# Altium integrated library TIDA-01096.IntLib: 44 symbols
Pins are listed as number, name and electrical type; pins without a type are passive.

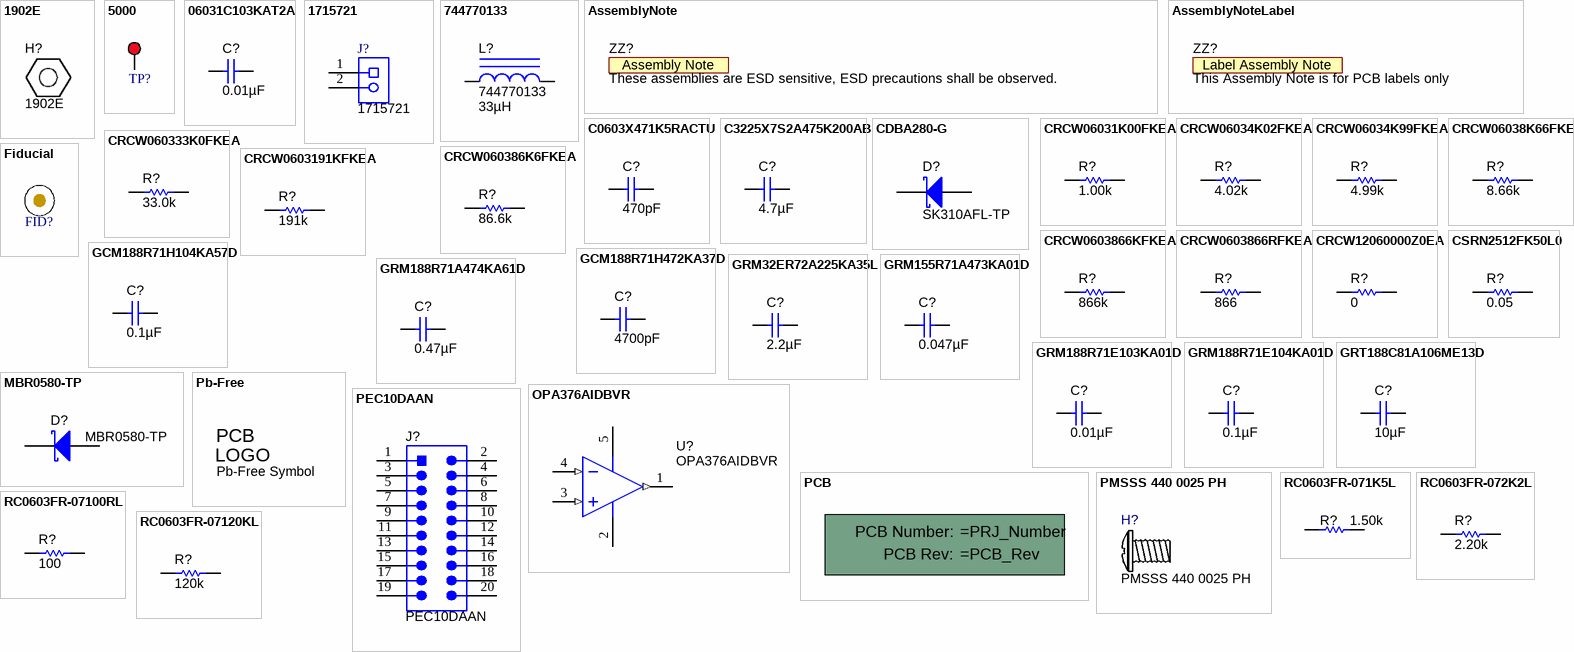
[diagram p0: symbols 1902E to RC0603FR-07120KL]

## 1902E
designator H?
Standoff, Hex, 1"L #4-40 Nylon; Manufacturer: Keystone; CompType: Hardware; SymbolCreator: a0412235
footprint Keystone_1902E

## 5000
designator TP?  (value not drawn)
Test Point, Miniature, Red, TH; Manufacturer: Keystone; CompType: Test Point Loop; U/M: EA
footprint Keystone5000
pins: 1

## 06031C103KAT2A
designator C?, comment ValueDisplayed: 0.01µF  (hidden comment: GCM188R72A103KA37D)
10000pF ±10% 100V X7R Ceramic Capacitor -55°C ~ 125°C Surface Mount, MLCC 0603 (1608 Metric) 0.063" L x 0.031" W (1.60mm x 0.80mm); Manufacturer: Murata Electronics North America; Polarized: N; Value: 0.01uF; U/M: EA; Cap_F: 0.00000001; Tolerance_%: 10; ESR_ohm: 0.098; Value1: 0.098 ohm; VDC_V: 100; TaMin_C: -55; TaMax_C: 125; Cap_Case: 0603; SizeArea_mm2: 1.28; SizeAreaWB_mm2: 4.68; SizeX_mm: 1.6; SizeY_mm: 0.8; SizeZ_mm: 1; AEC Category: Q200
signal-integrity model Cap
simulation model Cap
footprint 0603
footprint 0603M
footprint 0603L
footprint 0603_HV
footprint 0603S
pins: 1, 2

## 1715721
designator J?
Terminal Block, 5.08 mm, 2x1, TH; Manufacturer: Phoenix Contact; SymbolCreator: a0412235; Pitch_mm: 5.08; Gender: Female; Row_Count: 1; ContactFinish: Tin; Current_A: 17.5; Voltage_V: 400; Cert_CSA: Y; Cert_CULUS: N
footprint PhoenixContact_1715721
pins: 1, 2

## 744770133
designator L?  ValueDisplayed: 33µH
Inductor, Shielded Drum Core, Ferrite, 33uH, 3.2A, 0.047 ohm, SMD; Manufacturer: Wurth Elektronik eiSos; Ind_H: 33.0E-6; Imax_A: 3.2; Irms: 3.2A @ 40C rise; Isat: 3.6A @ 10% inductance drop; DCR_ohm: 0.047; U/M: EA
signal-integrity model Inductor
simulation model Inductor
footprint WE-PD-XL
pins: 1, 2

## AssemblyNote
designator ZZ?, comment These assemblies are ESD sensitive, ESD precautions shall be observed.  (no BOM)
SymbolCreator: codlsc; CompType: AssemblyNote
footprint AssemblyNote

## AssemblyNoteLabel
designator ZZ?, comment This Assembly Note is for PCB labels only  (no BOM)
SymbolCreator: a0412235
footprint AssemblyNoteLabel

## C0603X471K5RACTU
designator C?  ValueDisplayed: 470pF  (hidden comment: C0603X471K5RACTU)
CAP, CERM, 470 pF, 50 V, +/- 10%, X7R, 0603; Manufacturer: Kemet; Polarized: N; CompType: Capacitor; Value: 470pF; U/M: EA; Cap_F: 0.00000000047; Tolerance_%: 10; Value1: Unknown; VDC_V: 50; Value2: 50V; TaMin_C: -55; TaMax_C: 125; Cap_Case: 0603; AEC Category: Q200; SizeArea_mm2: 1.28; SizeAreaWB_mm2: 4.68; SizeX_mm: 1.6; SizeY_mm: 0.8; SizeZ_mm: 1
signal-integrity model Cap
simulation model Cap
footprint 0603
footprint 0603M
footprint 0603L
footprint 0603_HV
footprint 0603S
pins: 1, 2

## C3225X7S2A475K200AB
designator C?, comment ValueDisplayed: 4.7µF  (hidden comment: GRJ32DC72A475KE11L)
4.7µF ±10% 100V X7S Ceramic Capacitor -55°C ~ 125°C Surface Mount, MLCC 1210 (3225 Metric) 0.126" L x 0.098" W (3.20mm x 2.50mm); Manufacturer: Murata Electronics North America; Polarized: N; Value: 4.7uF; U/M: EA; Cap_F: 0.0000047; Tolerance_%: 10; ESR_ohm: 0.004236; Value1: 0.004236 ohm; VDC_V: 100; IRMS_A: 3.57337; TaMin_C: -55; TaMax_C: 125; Cap_Case: 1210_220; SizeArea_mm2: 8; SizeAreaWB_mm2: 14.7; SizeX_mm: 3.2; SizeY_mm: 2.5; SizeZ_mm: 2.2; AEC Category: Q200
signal-integrity model Cap
simulation model Cap
footprint 1210_220
footprint 1210_220M
footprint 1210_220L
pins: 1, 2

## CDBA280-G
designator D?, comment SK310AFL-TP
DIODE SCHOTTKY 100V 3A DO221AC; Manufacturer: Micro Commercial Co; U/M: EA; Vf_V: 0.85; Value: 80V; Value1: 2A; Value2: 0.85V; Io_A: 2; Vr_V: 80; TJmax_C: 125; SizeAreaWB_mm2: 37.3428; SizeArea_mm2: 16.3228; SizeX_mm: 5.59; SizeY_mm: 2.92; SizeZ_mm: 2.87; AEC Category: Q101
signal-integrity model Diode
footprint SMA
pins: 1 K, 2 A

## CRCW06031K00FKEA
designator R?  ValueDisplayed: 1.00k  (hidden comment: CRCW06031K00FKEA)
RES, 1.00 k, 1%, 0.1 W, 0603; Manufacturer: Vishay-Dale; CompType: Resistor; Value: 1.00k; Res_ohm: 1000; Value_Code: 1k00; Tolerance_%: 1; Power_W: 0.1; Value2: 0.1W; VDC_V: 75; TempCo: 100 ppm/C; SizeArea_mm2: 1.28; SizeX_mm: 1.6; SizeY_mm: 0.8; EIA_Code: E96; U/M: EA; AEC Category: Q200
signal-integrity model Resistor
simulation model Resistor
footprint 0603
footprint 0603M
footprint 0603L
footprint 0603_HV
footprint 0603S
pins: 1, 2

## CRCW06034K02FKEA
designator R?  ValueDisplayed: 4.02k  (hidden comment: CRCW06034K02FKEA)
RES, 4.02 k, 1%, 0.1 W, 0603; Manufacturer: Vishay-Dale; CompType: Resistor; Value: 4.02k; Res_ohm: 4020; Value_Code: 4k02; Tolerance_%: 1; Power_W: 0.1; Value2: 0.1W; VDC_V: 75; TempCo: 100 ppm/C; SizeArea_mm2: 1.28; SizeX_mm: 1.6; SizeY_mm: 0.8; EIA_Code: E96; U/M: EA; AEC Category: Q200
signal-integrity model Resistor
simulation model Resistor
footprint 0603
footprint 0603M
footprint 0603L
footprint 0603_HV
footprint 0603S
pins: 1, 2

## CRCW06034K99FKEA
designator R?  ValueDisplayed: 4.99k  (hidden comment: CRCW06034K99FKEA)
RES, 4.99 k, 1%, 0.1 W, 0603; Manufacturer: Vishay-Dale; CompType: Resistor; Value: 4.99k; Res_ohm: 4990; Value_Code: 4k99; Tolerance_%: 1; Power_W: 0.1; Value2: 0.1W; VDC_V: 75; TempCo: 100 ppm/C; SizeArea_mm2: 1.28; SizeX_mm: 1.6; SizeY_mm: 0.8; EIA_Code: E96; U/M: EA; AEC Category: Q200
signal-integrity model Resistor
simulation model Resistor
footprint 0603
footprint 0603M
footprint 0603L
footprint 0603_HV
footprint 0603S
pins: 1, 2

## CRCW06038K66FKEA
designator R?  ValueDisplayed: 8.66k  (hidden comment: CRCW06038K66FKEA)
RES, 8.66 k, 1%, 0.1 W, 0603; Manufacturer: Vishay-Dale; CompType: Resistor; Value: 8.66k; Res_ohm: 8660; Value_Code: 8k66; Tolerance_%: 1; Power_W: 0.1; Value2: 0.1W; VDC_V: 75; TempCo: 100 ppm/C; EIA_Code: E96; U/M: EA; AEC Category: Q200; SizeArea_mm2: 1.28; SizeX_mm: 1.6; SizeY_mm: 0.8
signal-integrity model Resistor
simulation model Resistor
footprint 0603
footprint 0603M
footprint 0603L
footprint 0603_HV
footprint 0603S
pins: 1, 2

## CRCW060333K0FKEA
designator R?  ValueDisplayed: 33.0k  (hidden comment: CRCW060333K0FKEA)
RES, 33.0 k, 1%, 0.1 W, 0603; Manufacturer: Vishay-Dale; CompType: Resistor; Value: 33.0k; Res_ohm: 33000; Value_Code: 33k0; Tolerance_%: 1; Power_W: 0.1; Value2: 0.1W; VDC_V: 75; TempCo: 100 ppm/C; U/M: EA; AEC Category: Q200; SizeArea_mm2: 1.28; SizeX_mm: 1.6; SizeY_mm: 0.8
signal-integrity model Resistor
simulation model Resistor
footprint 0603
footprint 0603M
footprint 0603L
footprint 0603_HV
footprint 0603S
pins: 1, 2

## CRCW060386K6FKEA
designator R?  ValueDisplayed: 86.6k  (hidden comment: CRCW060386K6FKEA)
RES, 86.6 k, 1%, 0.1 W, 0603; Manufacturer: Vishay-Dale; CompType: Resistor; Value: 86.6k; Res_ohm: 86600; Value_Code: 86k6; Tolerance_%: 1; Power_W: 0.1; Value2: 0.1W; VDC_V: 75; TempCo: 100 ppm/C; EIA_Code: E96; U/M: EA; AEC Category: Q200
signal-integrity model Resistor
simulation model Resistor
footprint 0603
footprint 0603M
footprint 0603L
footprint 0603_HV
footprint 0603S
pins: 1, 2

## CRCW0603191KFKEA
designator R?  ValueDisplayed: 191k  (hidden comment: CRCW0603191KFKEA)
RES, 191 k, 1%, 0.1 W, 0603; Manufacturer: Vishay-Dale; CompType: Resistor; Value: 191k; Res_ohm: 191000; Tolerance_%: 1; Power_W: 0.1; Value2: 0.1W; VDC_V: 75; TempCo: 100 ppm/C; SizeArea_mm2: 1.28; SizeX_mm: 1.6; SizeY_mm: 0.8; EIA_Code: E96; U/M: EA; AEC Category: Q200
signal-integrity model Resistor
simulation model Resistor
footprint 0603
footprint 0603M
footprint 0603L
footprint 0603_HV
footprint 0603S
pins: 1, 2

## CRCW0603866KFKEA
designator R?  ValueDisplayed: 866k  (hidden comment: CRCW0603866KFKEA)
RES, 866 k, 1%, 0.1 W, 0603; Manufacturer: Vishay-Dale; CompType: Resistor; Value: 866k; Res_ohm: 866000; Tolerance_%: 1; Power_W: 0.1; Value2: 0.1W; VDC_V: 75; TempCo: 100 ppm/C; EIA_Code: E96; U/M: EA; AEC Category: Q200; SizeArea_mm2: 1.28; SizeX_mm: 1.6; SizeY_mm: 0.8
signal-integrity model Resistor
simulation model Resistor
footprint 0603
footprint 0603M
footprint 0603L
footprint 0603_HV
footprint 0603S
pins: 1, 2

## CRCW0603866RFKEA
designator R?  ValueDisplayed: 866  (hidden comment: CRCW0603866RFKEA)
RES, 866, 1%, 0.1 W, 0603; Manufacturer: Vishay-Dale; CompType: Resistor; Value: 866; Value_Code: 866R; Tolerance_%: 1; Power_W: 0.1; Value2: 0.1W; VDC_V: 75; TempCo: 100 ppm/C; EIA_Code: E96; U/M: EA; AEC Category: Q200; SizeArea_mm2: 1.28; SizeX_mm: 1.6; SizeY_mm: 0.8
signal-integrity model Resistor
simulation model Resistor
footprint 0603
footprint 0603M
footprint 0603L
footprint 0603_HV
footprint 0603S
pins: 1, 2

## CRCW12060000Z0EA
designator R?  ValueDisplayed: 0  (hidden comment: CRCW12060000Z0EA)
RES, 0, 5%, 0.25 W, 1206; Manufacturer: Vishay-Dale; CompType: Resistor; Value: 0; Value_Code: 0000; Tolerance_%: 5; Power_W: 0.25; Value2: 0.25W; VDC_V: 200; TempCo: 200 ppm/C; EIA_Code: E24; U/M: EA; AEC Category: Q200; SizeArea_mm2: 5.12; SizeX_mm: 3.2; SizeY_mm: 1.6; SizeZ_mm: 1.35
signal-integrity model Resistor
simulation model Resistor
footprint 1206
footprint 1206M
footprint 1206L
pins: 1, 2

## CSRN2512FK50L0
designator R?, comment ValueDisplayed: 0.05  (hidden comment: CSRN2512FK50L0CT-ND)
RES, 0.05, 1%, 2 W, 2512; Manufacturer: Stackpole Electronics Inc; CompType: Resistor; Value: 0.05; Value_Code: R050; Tolerance_%: 1; Power_W: 2; Value2: 2W; TempCo: 200 ppm/C; EIA_Code: E96; U/M: EA; AEC Category: Q200
signal-integrity model Resistor
simulation model Resistor
footprint 2512
footprint 2512M
footprint 2512L
pins: 1, 2

## Fiducial
designator FID?  (value not drawn)
Fiducial mark.  There is nothing to buy or mount.; SymbolCreator: codlsc
footprint Fiducial10-30
footprint Fiducial10-20
footprint Fiducial15-30
footprint Fiducial20-40
footprint Fiducial6.4-20

## GCM188R71H104KA57D
designator C?  ValueDisplayed: 0.1µF  (hidden comment: GCM188R71H104KA57D)
CAP, CERM, 0.1 µF, 50 V, +/- 10%, X7R, 0603; Manufacturer: MuRata; Polarized: N; CompType: Capacitor; Value: 0.1uF; U/M: EA; Cap_F: 0.0000001; Tolerance_%: 10; ESR_ohm: 0.02; Value1: 0.02 ohm; VDC_V: 50; Value2: 50V; IRMS_A: 1.84; TaMin_C: -55; TaMax_C: 125; Cap_Case: 0603; SizeArea_mm2: 1.28; SizeAreaWB_mm2: 4.68; SizeX_mm: 1.6; SizeY_mm: 0.8; SizeZ_mm: 1; AEC Category: Q200
signal-integrity model Cap
simulation model Cap
footprint 0603
footprint 0603M
footprint 0603L
footprint 0603_HV
footprint 0603S
pins: 1, 2

## GCM188R71H472KA37D
designator C?, comment ValueDisplayed: 4700pF  (hidden comment: GCM188R72A103KA37D)
10000pF ±10% 100V X7R Ceramic Capacitor -55°C ~ 125°C Surface Mount, MLCC 0603 (1608 Metric) 0.063" L x 0.031" W (1.60mm x 0.80mm); Manufacturer: Maruta; Polarized: N; Value: 4700pF; U/M: EA; Cap_F: 0.0000000047; Tolerance_%: 10; Value1: Unknown; VDC_V: 50; Value2: 50V; TaMin_C: -55; TaMax_C: 125; Cap_Case: 0603; AEC Category: Q200; AEC Qualified: Y; AEC Grade: 1
signal-integrity model Cap
simulation model Cap
footprint 0603
footprint 0603M
footprint 0603L
footprint 0603_HV
footprint 0603S
pins: 1, 2

## GRM32ER72A225KA35L
designator C?  ValueDisplayed: 2.2µF  (hidden comment: GRM32ER72A225KA35L)
CAP, CERM, 2.2 µF, 100 V, +/- 10%, X7R, 1210; Manufacturer: MuRata; Polarized: N; CompType: Capacitor; Value: 2.2uF; U/M: EA; Cap_F: 0.0000022; Tolerance_%: 10; ESR_ohm: 0.007; Value1: 0.007 ohm; VDC_V: 100; Value2: 100V; IRMS_A: 4.4; TaMin_C: -55; TaMax_C: 125; Cap_Case: 1210; AEC Category: Q200
signal-integrity model Cap
simulation model Cap
footprint 1210_270
footprint 1210_270M
footprint 1210_270L
pins: 1, 2

## GRM155R71A473KA01D
designator C?  ValueDisplayed: 0.047µF  (hidden comment: GRM155R71A473KA01D)
CAP, CERM, 0.047 µF, 10 V, +/- 10%, X7R, 0402; Manufacturer: MuRata; Polarized: N; CompType: Capacitor; Value: 0.047uF; U/M: EA; Cap_F: 0.000000047; Tolerance_%: 10; Value1: Unknown; Value2: 10V; TaMin_C: -55; TaMax_C: 125; Cap_Case: 0402; AEC Category: Q200; SizeArea_mm2: 0.5; SizeAreaWB_mm2: 3; SizeX_mm: 1; SizeZ_mm: 0.6
signal-integrity model Cap
simulation model Cap
footprint 0402
footprint 0402M
footprint 0402L
footprint 0402S
pins: 1, 2

## GRM188R71A474KA61D
designator C?  ValueDisplayed: 0.47µF  (hidden comment: GRM188R71A474KA61D)
CAP, CERM, 0.47 µF, 10 V, +/- 10%, X7R, 0603; Manufacturer: MuRata; Polarized: N; CompType: Capacitor; Value: 0.47uF; U/M: EA; Cap_F: 0.00000047; Tolerance_%: 10; Value1: Unknown; Value2: 10V; TaMin_C: -55; TaMax_C: 125; Cap_Case: 0603; AEC Category: Q200; SizeArea_mm2: 1.28; SizeAreaWB_mm2: 4.68; SizeX_mm: 1.6; SizeY_mm: 0.8; SizeZ_mm: 1
signal-integrity model Cap
simulation model Cap
footprint 0603
footprint 0603M
footprint 0603L
footprint 0603_HV
footprint 0603S
pins: 1, 2

## GRM188R71E103KA01D
designator C?  ValueDisplayed: 0.01µF  (hidden comment: GRM188R71E103KA01D)
CAP, CERM, 0.01 µF, 25 V, +/- 10%, X7R, 0603; Manufacturer: MuRata; Polarized: N; CompType: Capacitor; Value: 0.01uF; U/M: EA; Cap_F: 0.00000001; Tolerance_%: 10; Value1: Unknown; VDC_V: 25; Value2: 25V; TaMin_C: -55; TaMax_C: 125; Cap_Case: 0603; SizeArea_mm2: 1.28; SizeAreaWB_mm2: 4.68; SizeX_mm: 1.6; SizeY_mm: 0.8; SizeZ_mm: 1; AEC Category: Q200
signal-integrity model Cap
simulation model Cap
footprint 0603
footprint 0603M
footprint 0603L
footprint 0603_HV
footprint 0603S
pins: 1, 2

## GRM188R71E104KA01D
designator C?  ValueDisplayed: 0.1µF  (hidden comment: GRM188R71E104KA01D)
CAP, CERM, 0.1 µF, 25 V, +/- 10%, X7R, 0603; Manufacturer: MuRata; Polarized: N; CompType: Capacitor; Value: 0.1uF; U/M: EA; Cap_F: 0.0000001; Tolerance_%: 10; Value1: Unknown; VDC_V: 25; Value2: 25V; TaMin_C: -55; TaMax_C: 125; Cap_Case: 0603; SizeArea_mm2: 1.28; SizeAreaWB_mm2: 4.68; SizeX_mm: 1.6; SizeY_mm: 0.8; SizeZ_mm: 1; AEC Category: Q200
signal-integrity model Cap
simulation model Cap
footprint 0603
footprint 0603M
footprint 0603L
footprint 0603_HV
footprint 0603S
pins: 1, 2

## GRT188C81A106ME13D
designator C?  ValueDisplayed: 10µF  (hidden comment: GRT188C81A106ME13D)
CAP, CERM, 10 µF, 10 V, +/- 20%, X6S, AEC-Q200 Grade 2, 0603; Manufacturer: MuRata; Polarized: N; CompType: Capacitor; Value: 10uF; U/M: EA; Cap_F: 0.00001; Tolerance_%: 20; Value1: Unknown; VDC_V: 10; Value2: 10V; TaMin_C: -55; TaMax_C: 105; Cap_Case: 0603; AEC Category: Q200; AEC Qualified: Y; AEC Grade: 2
signal-integrity model Cap
simulation model Cap
footprint 0603
footprint 0603M
footprint 0603L
footprint 0603_HV
footprint 0603S
pins: 1, 2

## MBR0580-TP
designator D?
Diode, Schottky, 80 V, 0.5 A, SOD-123; Manufacturer: Micro Commercial Components; U/M: EA; Vf_V: 0.8; Value: 80V; Value1: 0.5A; Value2: 0.8V; Io_A: 0.5; Vr_V: 80; TJmax_C: 150; SizeAreaWB_mm2: 13.095; SizeArea_mm2: 6.545; SizeX_mm: 3.85; SizeY_mm: 1.7; SizeZ_mm: 1.35; AEC Category: Q101
signal-integrity model Diode
footprint SOD-123
pins: 1 K, 2 A

## OPA376AIDBVR
designator U?
Precision, Low Noise, Low Iq Operational Amplifier, 2.2 to 5.5 V, -40 to 125 degC, 5-pin SOT23 (DBV0005A), Green (RoHS & no Sb/Br); Manufacturer: Texas Instruments; Alternate PartNumber: Equivalent; CMRR(Min)(dB): 76; IIB(Max)(pA): 10; Iq per channel(Max)(mA): 0.95; Number of Channels: 1; Offset Drift(Typ)(uV/C): 0.32; Slew Rate(Typ)(V/us): 2; Sub Family: Low Input Bias Current Amp (<=10pA), Low Noise Amp (<=10nV/rtHz), Low Offset Voltage Amplifier (<=500uV), Low Supply Voltage Amplifier (<=2.7V), Precision Amplifier; Total Supply Voltage(Max)(+5V is 5, +/-5V is 10): 5.5; Total Supply Voltage(Min)(+5V is 5, +/-5V is 10): 2.2; Vio (25C)(Max)(mV): 0.025; Vn at 1kHz(Typ)(nV/rtHz): 7.5
footprint DBV0005A_N (SOT23, 5-Leads, Body 2.9x1.6mm, Pitch 0.95mm, IPC Medium Density)
footprint DBV0005A_L (SOT23, 5-Leads, Body 2.9x1.6mm, Pitch 0.95mm, IPC Low Density)
footprint DBV0005A_M (SOT23, 5-Leads, Body 2.9x1.6mm, Pitch 0.95mm, IPC Low Density)
pins: 1 OUT (out), 2 V- (power), 3 IN+ (in), 4 IN- (in), 5 V+ (power)

## Pb-Free
designator Logo?, comment Pb-Free Symbol  (no BOM)
SymbolCreator: a0412235
footprint Pb-Free_Overlay_Medium
footprint Pb-Free_Overlay_Small

## PCB
designator !PCB?, comment Printed Circuit Board  (value not drawn)  (mechanical)
Manufacturer: Any; SymbolCreator: a0412235; CompType: PCB
1 alternate drawing of the same symbol

## PEC10DAAN
designator J?
Header, 100mil, 10x2, TH; Manufacturer: Sullins Connector Solutions; SymbolCreator: a0412235; U/M: EA
footprint SULLINS_PEC10DAAN
pins: 1, 2, 3, 4, 5, 6, 7, 8, 9, 10, 11, 12, 13, 14, 15, 16, 17, 18, 19, 20

## PMSSS 440 0025 PH
designator H?
MACHINE SCREW PAN PHILLIPS 4-40; Manufacturer: B&F Fastener Supply; CompType: Standoff; SymbolCreator: a0412235
footprint B_F_PMSSS4400025PH

## RC0603FR-071K5L
designator R?  ValueDisplayed: 1.50k  (hidden comment: RC0603FR-071K5L)
RES, 1.50 k, 1%, 0.1 W, 0603; Manufacturer: Yageo America; CompType: Resistor; Value: 1.50k; Res_ohm: 1500; Value_Code: 1k50; Tolerance_%: 1; Power_W: 0.1; Value2: 0.1W; VDC_V: 150; TempCo: 200 ppm/C; EIA_Code: E96; U/M: EA; AEC Category: Q200
signal-integrity model Resistor
simulation model Resistor
footprint 0603
footprint 0603M
footprint 0603L
footprint 0603_HV
footprint 0603S
pins: 1, 2

## RC0603FR-072K2L
designator R?, comment ValueDisplayed: 2.20k  (hidden comment: CRCW06032K20FKEA)
RES SMD 2.2K OHM 1% 1/10W 0603; Manufacturer: Vishay Dale; CompType: Resistor; Value: 2.20k; Res_ohm: 2200; Value_Code: 2k20; Tolerance_%: 1; Power_W: 0.1; Value2: 0.1W; VDC_V: 150; TempCo: 200 ppm/C; U/M: EA; AEC Category: Q200; SizeArea_mm2: 1.28; SizeX_mm: 1.6; SizeY_mm: 0.8
signal-integrity model Resistor
simulation model Resistor
footprint 0603
footprint 0603M
footprint 0603L
footprint 0603_HV
footprint 0603S
pins: 1, 2

## RC0603FR-07100RL
designator R?  ValueDisplayed: 100  (hidden comment: RC0603FR-07100RL)
RES, 100, 1%, 0.1 W, 0603; Manufacturer: Yageo America; CompType: Resistor; Value: 100; Value_Code: 100R; Tolerance_%: 1; Power_W: 0.1; Value2: 0.1W; VDC_V: 150; TempCo: 200 ppm/C; EIA_Code: E96; U/M: EA; AEC Category: Q200
signal-integrity model Resistor
simulation model Resistor
footprint 0603
footprint 0603M
footprint 0603L
footprint 0603_HV
footprint 0603S
pins: 1, 2

## RC0603FR-07120KL
designator R?, comment ValueDisplayed: 120k  (hidden comment: CRCW0603120KFKEA)
RES SMD 120K OHM 1% 1/10W 0603; Manufacturer: Vishay Dale; CompType: Resistor; Res_ohm: 120000; Tolerance_%: 1; Power_W: 0.1; Value2: 0.1W; VDC_V: 150; TempCo: 200 ppm/C; SizeArea_mm2: 1.28; SizeX_mm: 1.6; SizeY_mm: 0.8; U/M: EA; AEC Category: Q200
signal-integrity model Resistor
simulation model Resistor
footprint 0603
footprint 0603M
footprint 0603L
footprint 0603_HV
footprint 0603S
pins: 1, 2

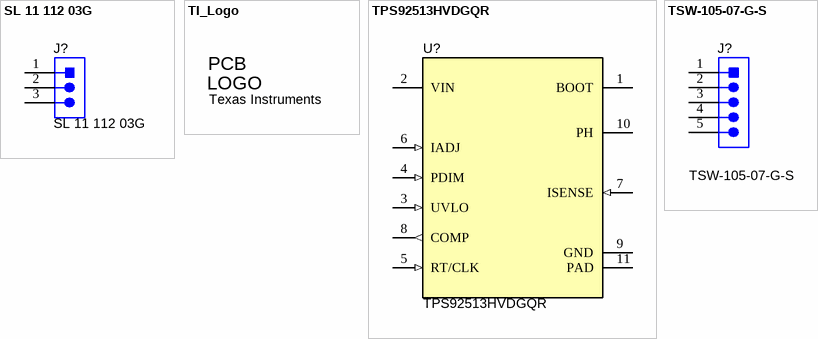
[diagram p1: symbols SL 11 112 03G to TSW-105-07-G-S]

## SL 11 112 03G
designator J?
Header, 2.54mm, 3x1, Gold, TH; Manufacturer: Fischer Elektronik; SymbolCreator: a0799628
footprint Fischer_SL-11-112-03G
pins: 1, 2, 3
3 alternate drawings of the same symbol

## TI_Logo
designator Logo?, comment Texas Instruments  (no BOM)
Texas Instrument Corporate Signature; SymbolCreator: codlsc
footprint TI_Stacked_SolderMask_Medium
footprint TI_Stacked_SolderMask_Small
footprint TI_Stacked_Overlay_Medium
footprint TI_Stacked_Overlay_Small
footprint TI_Horizontal_SolderMask_Medium
footprint TI_Horizontal_SolderMask_Small
footprint TI_Horizontal_Overlay_Medium
footprint TI_Horizontal_Overlay_Small
footprint TI_Symbol_SolderMask_Small
footprint TI_Symbol_Overlay_Medium
footprint TI_Symbol_Overlay_Small
footprint TI_Symbol_SolderMask_Medium

## TPS92513HVDGQR
designator U?
1.5A Buck LED Driver with Integrated Analog Current Adjust, DGQ0010D; Alternate PartNumber: TPS92513HVDGQT; Manufacturer: Texas Instruments; SymbolCreator: a0411947; SizeArea_mm2: 14.7; SizeAreaWB_mm2: 23.6; SizeX_mm: 4.9; SizeY_mm: 3; SizeZ_mm: 1.1; CompType: IC; U/M: EA
footprint DGQ0010D_N
footprint DGQ0010D_M
footprint DGQ0010D_L
footprint DGQ0010D_NV_N
footprint DGQ0010D_NV_M
footprint DGQ0010D_NV_L
pins: 1 BOOT (power), 2 VIN (power), 3 UVLO (in), 4 PDIM (in), 5 RT/CLK (in), 6 IADJ (in), 7 ISENSE (in), 8 COMP (out), 9 GND (power), 10 PH (power), 11 PAD (power)
1 alternate drawing of the same symbol

## TSW-105-07-G-S
designator J?
Header, 100mil, 5x1, Gold, TH; Manufacturer: Samtec; SymbolCreator: a0412235; U/M: EA
footprint TSW-105-07-G-S
footprint TSW-105-07-X-S
pins: 1, 2, 3, 4, 5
